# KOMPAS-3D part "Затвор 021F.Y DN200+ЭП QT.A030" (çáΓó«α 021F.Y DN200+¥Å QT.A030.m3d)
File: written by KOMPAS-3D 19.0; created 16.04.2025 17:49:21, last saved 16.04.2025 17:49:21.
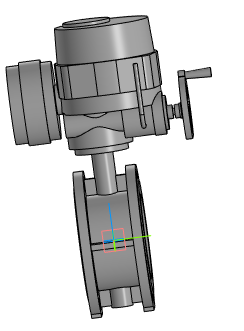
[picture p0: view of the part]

Document properties: Полное имя файла: Затвор 021F.Y DN200+ЭП QT.A030.a3d

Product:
- Part/product: Затвор 021F.Y DN200+ЭП QT.A030
    Масса: 146.462

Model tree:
1. Операция без истории:1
